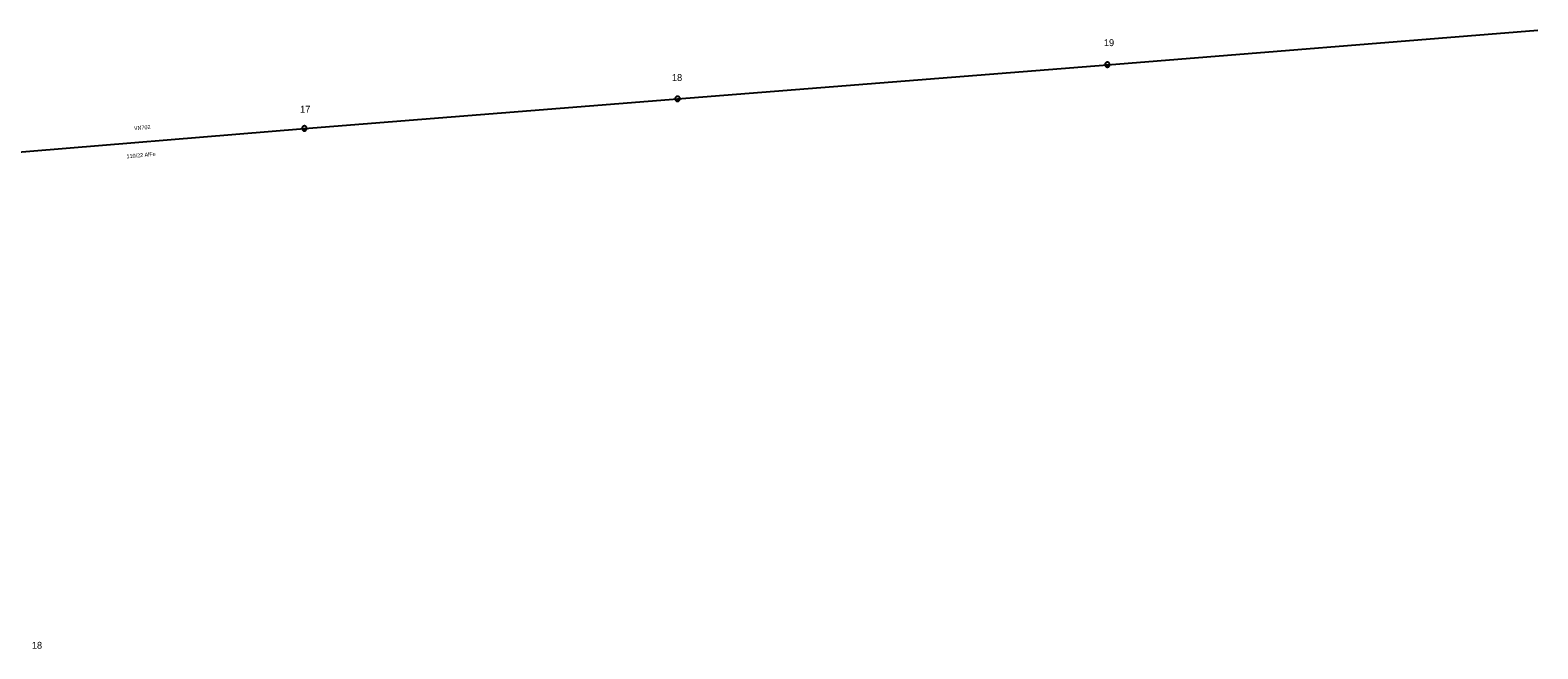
# Model space of a CAD drawing. Extents: x -545588 to -543214, y -1196037 to -1194452.
# Drawn here: x -543597.4 to -543214, y -1195997.2 to -1195839.9 of the extents above; entities that cross this region are included whole.
import ezdxf

# ---------------------------------------------------------------- set-up
doc = ezdxf.new("R2010")
doc.units = 0
for name, color, linetype in [('DOPLŇ_POPISY', 7, 'Continuous'), ('ELE_EON', 7, 'Continuous'), ('ELE_EON_POPIS', 7, 'Continuous'), ('POL_ZNAČKA_PRACOVNÍ', 7, 'Continuous'), ('SDEL_EON', 7, 'Continuous')]:
    doc.layers.add(name, color=color, linetype=linetype)

# ---------------------------------------------------------------- blocks, each defined once
blk = doc.blocks.new('VN440')
at = {"layer": 'ELE_EON_POPIS'}
for points in [[(1.22, 0), (1.21, 0.13), (1.19, 0.25), (1.16, 0.38), (1.11, 0.5), (1.05, 0.61), (0.98, 0.72), (0.9, 0.82), (0.81, 0.91), (0.71, 0.99), (0.6, 1.06), (0.49, 1.12), (0.37, 1.16), (0.25, 1.2), (0.12, 1.22), (-0.01, 1.22), (-0.14, 1.22), (-0.26, 1.2), (-0.39, 1.16), (-0.51, 1.12), (-0.62, 1.06), (-0.73, 0.99), (-0.83, 0.91), (-0.92, 0.82), (-1, 0.72), (-1.07, 0.61), (-1.13, 0.5), (-1.18, 0.38), (-1.21, 0.25), (-1.23, 0.13), (-1.24, 0), (-1.23, -0.13), (-1.21, -0.26), (-1.18, -0.38), (-1.13, -0.5), (-1.07, -0.62), (-1, -0.73), (-0.92, -0.83), (-0.83, -0.92), (-0.73, -1), (-0.62, -1.07), (-0.51, -1.13), (-0.39, -1.17), (-0.26, -1.2), (-0.14, -1.23), (-0.01, -1.23), (0.12, -1.23), (0.25, -1.2), (0.37, -1.17), (0.49, -1.13), (0.6, -1.07), (0.71, -1), (0.81, -0.92), (0.9, -0.83), (0.98, -0.73), (1.05, -0.62), (1.11, -0.5), (1.16, -0.38), (1.19, -0.26), (1.21, -0.13), (1.22, 0)], [(-1.24, 0), (1.22, 0)], [(-1.18, -0.34), (1.1, -0.34)], [(-1.01, -0.63), (0.97, -0.63)], [(-0.74, -0.92), (0.68, -0.92)]]:
    blk.add_lwpolyline(points, dxfattribs=at)

msp = doc.modelspace()

# ---------------------------------------------------------------- linework, layer by layer
at = {"layer": 'ELE_EON'}
msp.add_lwpolyline([(-543605.83, -1195871.31), (-543527.67, -1195864.84), (-543432.77, -1195857.32), (-543323.46, -1195848.64), (-543214.01, -1195839.86)], dxfattribs=at)

# ---------------------------------------------------------------- block references
at = {"layer": 'DOPLŇ_POPISY'}
for p, xscale, yscale, rotation in [((-543323.46, -1195848.64), 0.49999999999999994, 0.5000000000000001, 4.544069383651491), ((-543432.77, -1195857.32), 0.5, 0.5, 4.530130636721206), ((-543527.67, -1195864.84), 0.5, 0.5, 4.762719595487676)]:
    msp.add_blockref('VN440', p, dxfattribs=dict(at, xscale=xscale, yscale=yscale, rotation=rotation))

# ---------------------------------------------------------------- texts
at = {"layer": 'ELE_EON_POPIS'}
msp.add_text('110/22 AlFe', height=1, rotation=4.763, dxfattribs=at).set_placement((-543572.87, -1195872.46))
at = {"layer": 'POL_ZNAČKA_PRACOVNÍ'}
for s, p in [('19', (-543324.36, -1195843.92)), ('18', (-543434.21, -1195852.78)), ('17', (-543528.77, -1195860.85)), ('18', (-543596.98, -1195997.2))]:
    msp.add_text(s, height=1.75, dxfattribs=at).set_placement(p)
at = {"layer": 'SDEL_EON'}
msp.add_text('VN702', height=1, rotation=4.763, dxfattribs=at).set_placement((-543570.98, -1195865.32))

doc.saveas('drawing.dxf')
